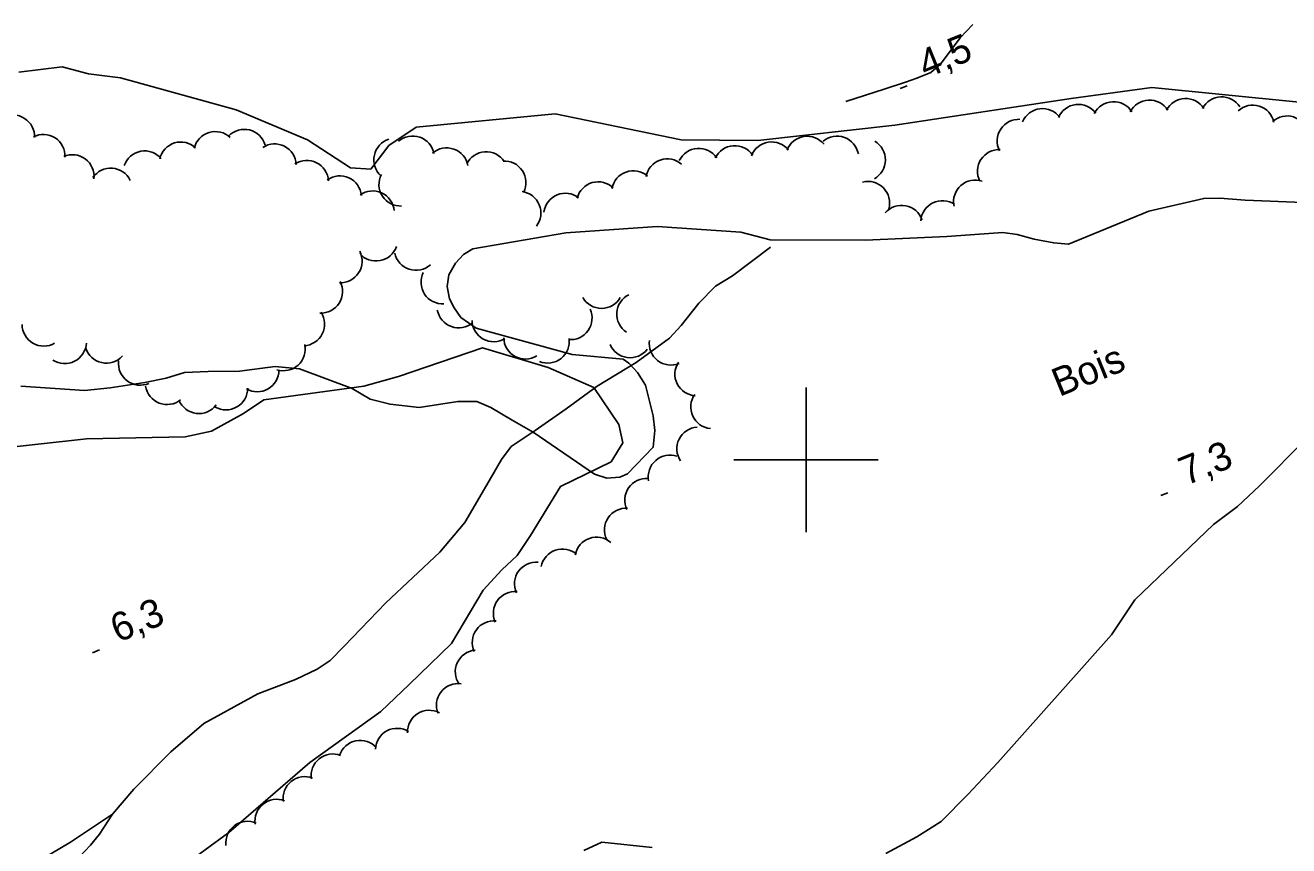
# Model space of a CAD drawing. Extents: x 362852 to 366875, y 5563573 to 5566479.
# Drawn here: x 365091.9 to 365266.8, y 5565146.6 to 5565260.2 of the extents above; entities that cross this region are included whole.
import ezdxf

# ---------------------------------------------------------------- set-up
doc = ezdxf.new("R2010")
doc.units = 0
for name, color, linetype in [('Niveau 2', 7, 'Continuous'), ('Niveau 22', 7, 'Continuous'), ('Niveau 3', 7, 'Continuous'), ('Niveau 44', 7, 'Continuous'), ('Niveau 61', 7, 'Continuous'), ('Niveau 7', 7, 'Continuous')]:
    doc.layers.add(name, color=color, linetype=linetype)

msp = doc.modelspace()

# ---------------------------------------------------------------- linework, layer by layer
at = {"layer": 'Niveau 2'}
for points in [[(365275.73, 5565235.36), (365260.79, 5565235.94), (365257.3, 5565236.25), (365255.07, 5565236.2), (365247.45, 5565234.44), (365236.36, 5565229.88), (365234.31, 5565230.03), (365231.6, 5565230.54), (365229.22, 5565231.18), (365227.23, 5565231.48), (365219.49, 5565230.91), (365208.23, 5565230.4), (365195.01, 5565230.44), (365190.95, 5565231.51), (365179.38, 5565232.31), (365166.72, 5565231.43), (365153.86, 5565229.22), (365152.57, 5565228.44), (365151.46, 5565227.24), (365150.52, 5565225.61), (365150.3, 5565224.02), (365150.64, 5565222.3), (365151.28, 5565221.07), (365152.21, 5565219.71), (365154.31, 5565218.22), (365167.6, 5565214.57), (365174.67, 5565213.96), (365175.46, 5565213.41), (365176.67, 5565212.11), (365177.78, 5565210.33), (365178.84, 5565206.11), (365179.05, 5565204.08), (365178.84, 5565201.75), (365175.28, 5565198.05)], [(365175.28, 5565198.05), (365174.22, 5565197.61), (365172.41, 5565197.48), (365170.7, 5565198.02), (365162.23, 5565203.84), (365159.31, 5565205.49), (365156.35, 5565207.26), (365154.41, 5565208.07), (365151.79, 5565208.1), (365146.43, 5565207.26), (365142.4, 5565207.71), (365139.62, 5565208.42), (365137.16, 5565209.89), (365129.84, 5565212.59), (365126.47, 5565212.94), (365121.54, 5565212.27), (365117.22, 5565212.22), (365113.92, 5565212.1), (365111.39, 5565211.31), (365108.42, 5565210.7), (365103.63, 5565209.96), (365100.06, 5565209.61), (365091.26, 5565210.2)], [(365211.06, 5565145.52), (365215.35, 5565147.79), (365218.71, 5565149.92), (365222.39, 5565153.67), (365226.54, 5565158.11), (365242.28, 5565175.79), (365245.53, 5565180.61), (365256.41, 5565191.06), (365259.74, 5565193.55), (365262.79, 5565196.42), (365269.31, 5565202.96)], [(365169.24, 5565145.91), (365171.73, 5565147.07), (365178.71, 5565146.35)]]:
    msp.add_lwpolyline(points, dxfattribs=at)
at = {"layer": 'Niveau 22'}
for points in [[(365205.52, 5565249.62), (365210.82, 5565251.3), (365213.79, 5565252.27), (365215.36, 5565252.85), (365217.28, 5565253.64), (365218.63, 5565254.76), (365221.36, 5565258.44), (365223.1, 5565260.28)], [(365099.34, 5565145.01), (365100.89, 5565146.64), (365102.18, 5565148.17), (365103.95, 5565150.95), (365106.91, 5565154.42), (365112.03, 5565159.57), (365116.61, 5565163.52), (365124.1, 5565167.61), (365129.31, 5565169.57), (365132.32, 5565171), (365134.1, 5565172.24), (365136.06, 5565174.23), (365141.83, 5565180.22), (365149.3, 5565187.22), (365152.75, 5565191.32), (365155.79, 5565196.55), (365157.82, 5565200.06), (365159.18, 5565201.87), (365162.49, 5565204.05), (365166.77, 5565207.06), (365171.06, 5565210.2), (365176.46, 5565213.49), (365181.1, 5565216.83), (365182.72, 5565218.62), (365185.17, 5565221.68), (365187.48, 5565224.07), (365189.82, 5565225.47), (365195.06, 5565229.44)], [(365103.95, 5565150.95), (365098.12, 5565147.06), (365092.69, 5565143.82), (365084.95, 5565138.82), (365076.5, 5565133.33), (365069.21, 5565127.52), (365062.45, 5565121.81), (365059.54, 5565117.62), (365056.56, 5565110.43), (365054.62, 5565102.86), (365053.34, 5565099.9)]]:
    msp.add_lwpolyline(points, dxfattribs=at)
at = {"layer": 'Niveau 3'}
for p, q in [((365213.05, 5565251.41), (365214.01, 5565251.8)), ((365249.12, 5565195.05), (365250.08, 5565195.44)), ((365101.18, 5565173.3), (365102.14, 5565173.69))]:
    msp.add_line(p, q, dxfattribs=at)
at = {"layer": 'Niveau 44'}
for centre, start, end in [((365247.57, 5565246.81), 32.5565, 152.5345), ((365252.57, 5565247.03), 32.5565, 152.5345), ((365257.56, 5565247.25), 32.5565, 152.5345), ((365232.74, 5565245.63), 36.6758, 156.6537), ((365237.71, 5565246.21), 36.6758, 156.6537), ((365242.58, 5565246.59), 32.5565, 152.5345), ((365261.86, 5565246.11), 12.5327, 132.5106), ((365090.17, 5565244.75), 357.3061, 117.284), ((365229.47, 5565244.15), 87.0082, 206.9862), ((365266.62, 5565244.61), 12.5327, 132.5106), ((365094.38, 5565242.05), 357.3061, 117.284), ((365118.21, 5565242.45), 46.8829, 166.8609), ((365122.22, 5565242.76), 15.9339, 135.9118), ((365145.52, 5565241.84), 10.8308, 130.8087), ((365200.17, 5565241.8), 39.018, 158.996), ((365204.29, 5565241.82), 10.119, 130.0969), ((365108.42, 5565239.77), 40.7031, 160.6811), ((365113.42, 5565241), 46.8829, 166.8609), ((365126.41, 5565240.74), 3.021, 122.9989), ((365143.15, 5565241.55), 107.6698, 227.6477), ((365150.24, 5565240.19), 10.8308, 130.8087), ((365185.15, 5565240.13), 34.2505, 154.2285), ((365190.14, 5565240.5), 34.2505, 154.2285), ((365195.24, 5565241.02), 39.018, 158.996), ((365207.99, 5565241.53), 299.6587, 59.6367), ((365226.74, 5565239.96), 87.0082, 206.9862), ((365098.41, 5565239.25), 353.6227, 113.6007), ((365130.86, 5565238.47), 3.021, 122.9989), ((365155.72, 5565239.65), 34.0318, 154.0098), ((365158.22, 5565238.38), 333.5232, 93.5011), ((365180.8, 5565238.67), 49.2603, 169.2382), ((365103.72, 5565237.39), 25.7625, 145.7404), ((365135.44, 5565236.32), 5.3673, 125.3452), ((365143.86, 5565238.14), 152.5601, 272.538), ((365176.07, 5565237.02), 49.2603, 169.2382), ((365171.22, 5565235.49), 45.7924, 165.7704), ((365208.58, 5565235.55), 344.5107, 104.4886), ((365223.43, 5565235.74), 71.5601, 191.538), ((365139.98, 5565234.23), 5.3673, 125.3452), ((365160.28, 5565234.17), 322.3935, 82.3715), ((365166.68, 5565233.91), 52.6412, 172.6192), ((365218.89, 5565232.89), 56.1595, 176.1375), ((365213.24, 5565232.24), 19.163, 139.1409), ((365135.52, 5565227.51), 267.2294, 27.2073), ((365140.45, 5565230.53), 221.0427, 341.0207), ((365145.98, 5565229.24), 191.751, 311.729), ((365149.68, 5565224.6), 153.3804, 273.3584), ((365132.81, 5565223.31), 267.2294, 27.2073), ((365171.68, 5565223.97), 210.232, 330.2099), ((365176.79, 5565220.18), 116.52, 236.498), ((365130.34, 5565218.8), 272.8608, 32.8388), ((365151.89, 5565221.28), 190.5742, 310.5521), ((365167.37, 5565219.64), 264.5608, 24.5387), ((365094.44, 5565218.75), 180.1659, 300.1439), ((365156.75, 5565219.36), 181.3513, 301.3292), ((365161.14, 5565216.96), 181.3513, 301.3292), ((365164.22, 5565216.4), 248.0486, 8.0265), ((365181.29, 5565216.12), 172.0378, 292.0158), ((365097.35, 5565216.33), 236.9274, 356.9054), ((365103.1, 5565216.39), 197.9364, 317.9144), ((365127.64, 5565215.34), 252.295, 12.273), ((365175.63, 5565217.14), 202.534, 322.5119), ((365107.79, 5565213.34), 173.2664, 293.2443), ((365184.84, 5565211.87), 146.5346, 266.5126), ((365124, 5565212.43), 240.1351, 0.113), ((365111.51, 5565210.66), 188.6773, 308.6553), ((365119.68, 5565209.92), 240.1351, 0.113), ((365115.93, 5565209.41), 202.8381, 322.816), ((365187.03, 5565207.32), 144.7238, 264.7017), ((365185.11, 5565201.54), 93.9481, 213.926), ((365181.15, 5565197.66), 70.9502, 190.9282), ((365177.9, 5565194.42), 85.373, 205.351), ((365175.09, 5565190.31), 86.2426, 206.2206), ((365170.99, 5565186.3), 49.1647, 169.1427), ((365166.27, 5565184.66), 49.1647, 169.1427), ((365162.62, 5565182.84), 84.3064, 204.2844), ((365159.7, 5565178.78), 84.3064, 204.2844), ((365156.78, 5565174.72), 84.3064, 204.2844), ((365154.43, 5565170.66), 95.1855, 215.1634), ((365151.81, 5565166.03), 81.7418, 201.7197), ((365147.81, 5565162.33), 61.9251, 181.903), ((365143.36, 5565159.83), 57.7008, 177.6787), ((365138.25, 5565158.17), 41.4385, 161.4164), ((365134.47, 5565156.29), 68.9667, 188.9446), ((365130.58, 5565153.15), 68.9667, 188.9446), ((365126.69, 5565150.01), 68.9667, 188.9446), ((365122.65, 5565146.96), 66.2868, 186.2647)]:
    msp.add_arc(centre, 3, start, end, dxfattribs=at)
at = {"layer": 'Niveau 61'}
for p, q in [((365200, 5565210), (365200, 5565190)), ((365190, 5565200), (365210, 5565200))]:
    msp.add_line(p, q, dxfattribs=at)
at = {"layer": 'Niveau 7'}
for points in [[(365292.71, 5565253.07), (365291.42, 5565250.42), (365287.49, 5565249.05), (365267.82, 5565249.57), (365247.88, 5565251.55), (365236.71, 5565250.05), (365212.31, 5565246.32), (365193.33, 5565244.2), (365182.73, 5565244.31), (365165.24, 5565247.9), (365146, 5565246.06), (365142.22, 5565243.5), (365139.72, 5565240.23), (365136.9, 5565240.43), (365130.95, 5565244.32), (365121.07, 5565248.44), (365105.07, 5565252.91), (365100.63, 5565253.44), (365096.99, 5565254.43), (365090.97, 5565253.68)], [(365086.09, 5565201.36), (365100.35, 5565202.9), (365114, 5565203.19), (365117.66, 5565203.95), (365122.1, 5565206.41), (365124.91, 5565208.32), (365138.78, 5565210.19), (365143.56, 5565211.54), (365155.19, 5565215.49), (365164.27, 5565212.77), (365170.6, 5565210.04), (365174.09, 5565204.89), (365174.63, 5565202.38), (365173, 5565199.72), (365165.99, 5565196.32), (365161.85, 5565189.52), (365160.01, 5565186.77), (365157.86, 5565184.76), (365155.3, 5565181.96), (365150.91, 5565174.56), (365145.06, 5565168.91), (365141.14, 5565165.17), (365131.28, 5565158.12), (365120.07, 5565148.4), (365110.24, 5565141.22)]]:
    msp.add_lwpolyline(points, dxfattribs=at)

# ---------------------------------------------------------------- texts
at = {"layer": 'Niveau 3'}
for s, p in [('4,5  ', (365216.56, 5565252.77)), ('7,3  ', (365252.63, 5565196.41)), ('6,3  ', (365104.69, 5565174.66))]:
    msp.add_text(s, height=3.93, rotation=22.09, dxfattribs=at).set_placement(p)
at = {"layer": 'Niveau 44'}
msp.add_text('Bois', height=3.93, rotation=22.09, dxfattribs=at).set_placement((365235.06, 5565208.69))

doc.saveas('drawing.dxf')
